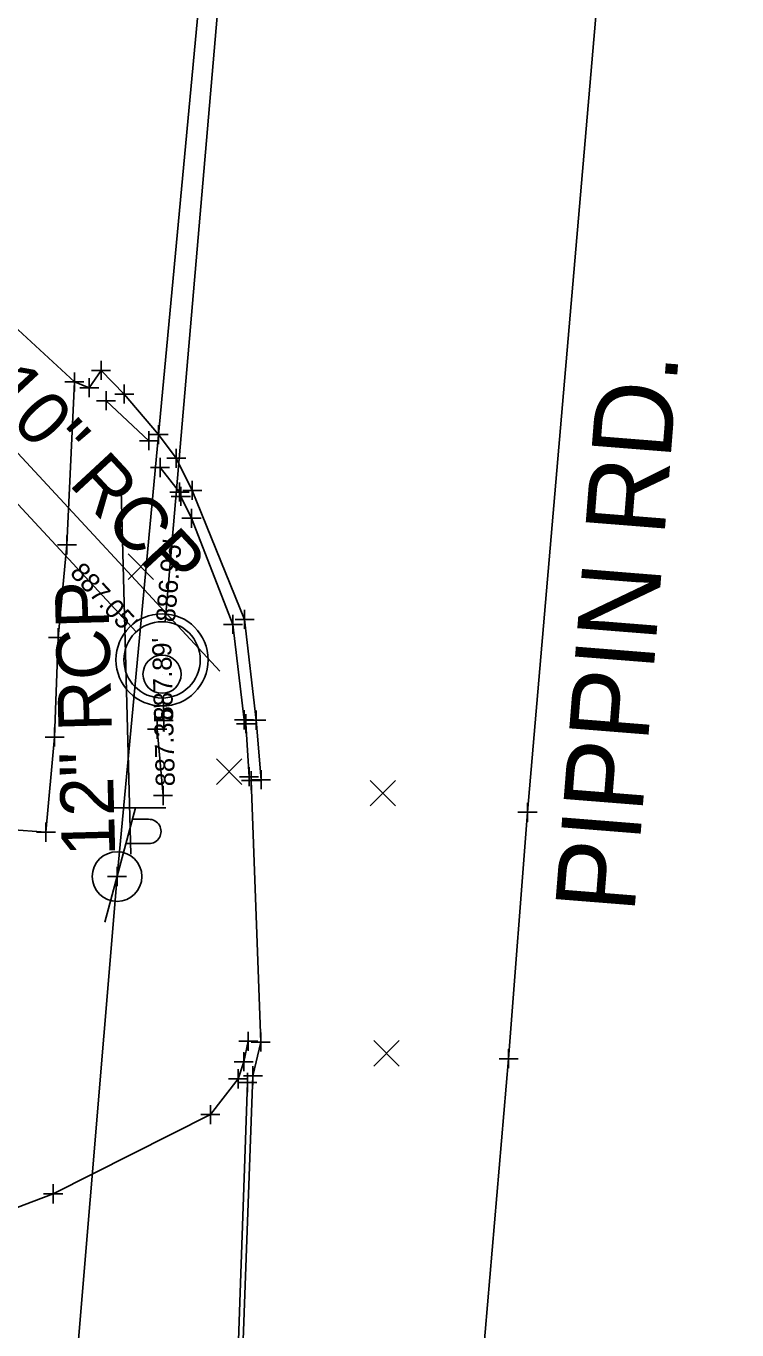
# Model space of a CAD drawing. Extents: x 1380550 to 1381945, y 468927 to 470496.
# Drawn here: x 1381555 to 1381592.3, y 469733.6 to 469802 of the extents above; entities that cross this region are included whole.
import ezdxf

# ---------------------------------------------------------------- set-up
doc = ezdxf.new("R2010")
doc.units = 0
for name, color, linetype in [('DR_X_Cells', 7, 'Continuous'), ('DR_X_Ditch', 7, 'Continuous'), ('DR_X_Elev_Flow', 7, 'Continuous'), ('DR_X_Storm_Sewer', 7, 'Continuous'), ('DR_X_Text', 7, 'Continuous'), ('GK_Drainage_Nodes', 7, 'Continuous'), ('PV_X_COP', 7, 'Continuous'), ('PV_X_Curb', 7, 'Continuous'), ('PV_X_Driveway', 7, 'Continuous'), ('PV_X_EOP', 7, 'Continuous'), ('PV_X_Walk', 7, 'Continuous'), ('RD_X_Text', 7, 'Continuous'), ('SC_Scratch1', 7, 'Continuous'), ('SV_X_Random_Point', 7, 'Continuous'), ('SV_X_Shot_Marker', 7, 'Continuous'), ('UT_X_Electric', 7, 'Continuous'), ('UT_X_Misc_Cells', 7, 'Continuous'), ('UT_X_Telecom', 7, 'Continuous')]:
    doc.layers.add(name, color=color, linetype=linetype)

msp = doc.modelspace()

# ---------------------------------------------------------------- linework, layer by layer
at = {"layer": 'DR_X_Cells'}
for centre, radius in [((1381562.133, 469768.763), 2.417), ((1381562.133, 469768.763), 2), ((1381562.133, 469768.013), 1)]:
    msp.add_circle(centre, radius, dxfattribs=at)
at = {"layer": 'DR_X_Ditch'}
msp.add_lwpolyline([(1381561.875, 469765.127), (1381562.186, 469761.653)], dxfattribs=at)
at = {"layer": 'DR_X_Elev_Flow'}
for p, q in [((1381562.218, 469766.087), (1381562.218, 469765.087)), ((1381561.718, 469765.587), (1381562.718, 469765.587)), ((1381562.218, 469765.587), (1381562.218, 469765.587))]:
    msp.add_line(p, q, dxfattribs=at)
at = {"layer": 'DR_X_Storm_Sewer'}
for p, q in [((1381562.304, 469770.756), (1381570.468, 469866.053)), ((1381551.192, 469780.565), (1381560.773, 469770.23)), ((1381562.218, 469765.587), (1381562.187, 469766.764))]:
    msp.add_line(p, q, dxfattribs=at)
at = {"layer": 'DR_X_Text'}
for p, q in [((1381565.163, 469768.167), (1381552.187, 469782.164)), ((1381559.994, 469777.663), (1381560.505, 469758.584))]:
    msp.add_line(p, q, dxfattribs=at)
at = {"layer": 'GK_Drainage_Nodes'}
for p, q in [((1381562.133, 469770.763), (1381562.133, 469770.763)), ((1381562.133, 469768.763), (1381562.133, 469768.763)), ((1381562.133, 469768.763), (1381562.133, 469768.763)), ((1381562.133, 469768.013), (1381562.133, 469768.013)), ((1381562.133, 469766.763), (1381562.133, 469766.763))]:
    msp.add_line(p, q, dxfattribs=at)
msp.add_circle((1381562.133, 469768.763), 2, dxfattribs=at)
at = {"layer": 'PV_X_COP'}
msp.add_lwpolyline([(1381585.986, 469815.579), (1381581.288, 469760.779), (1381580.3, 469747.86), (1381578.724, 469729.445), (1381576.782, 469708.953), (1381575.288, 469689.792), (1381572.756, 469657.561), (1381569.364, 469615.703), (1381565.36, 469567.235), (1381561.161, 469537.516), (1381558.939, 469486.814), (1381555.385, 469442.034), (1381550.974, 469391.016), (1381547.282, 469345.901), (1381541.953, 469289.547), (1381537.187, 469231.269), (1381533.052, 469168.087), (1381530.317, 469133.741), (1381523.968, 469065.081), (1381520.119, 469021.37), (1381518.183, 469001.306)], dxfattribs=at)
at = {"layer": 'PV_X_Curb'}
for points in [[(1381559.2, 469782.348), (1381561.446, 469780.248)], [(1381562.028, 469778.847), (1381563.047, 469777.556)], [(1381563.117, 469777.334), (1381563.677, 469776.185), (1381565.845, 469770.624), (1381566.43, 469765.622)], [(1381566.528, 469765.416), (1381566.694, 469762.642)], [(1381566.655, 469748.774), (1381566.415, 469747.703), (1381566.122, 469746.805)]]:
    msp.add_lwpolyline(points, dxfattribs=at)
at = {"layer": 'PV_X_Driveway'}
for points in [[(1381566.122, 469746.805), (1381564.669, 469744.932), (1381556.427, 469740.777), (1381548.721, 469737.856), (1381530.445, 469739.354), (1381510.464, 469741.163), (1381499.816, 469742.492)], [(1381566.606, 469746.613), (1381566.048, 469730.586), (1381565.129, 469713.089)]]:
    msp.add_lwpolyline(points, dxfattribs=at)
at = {"layer": 'PV_X_EOP'}
msp.add_lwpolyline([(1381504.028, 469796.448), (1381535.807, 469794.23), (1381542.352, 469793.559), (1381553.913, 469786.695), (1381557.537, 469783.333), (1381558.315, 469783.028), (1381558.933, 469783.936), (1381560.152, 469782.697), (1381561.946, 469780.572), (1381562.877, 469779.327), (1381563.718, 469777.647), (1381566.457, 469770.887), (1381567.072, 469765.604), (1381567.323, 469762.484), (1381566.8, 469762.436), (1381567.306, 469748.735), (1381566.899, 469746.966), (1381566.292, 469730.736), (1381565.481, 469712.75), (1381565.267, 469710.062), (1381564.074, 469691.212), (1381563.724, 469691.131), (1381563.046, 469684.218)], dxfattribs=at)
at = {"layer": 'PV_X_Walk'}
msp.add_lwpolyline([(1381557.537, 469783.333), (1381557.146, 469774.789), (1381556.682, 469769.93), (1381556.498, 469764.719), (1381556.044, 469759.732), (1381552.219, 469760.017)], dxfattribs=at)
at = {"layer": 'SV_X_Random_Point'}
for p, q in [((1381560.354, 469772.978), (1381561.688, 469774.313)), ((1381560.354, 469774.313), (1381561.688, 469772.978)), ((1381564.979, 469762.233), (1381566.313, 469763.568)), ((1381564.979, 469763.568), (1381566.313, 469762.233)), ((1381573.034, 469761.107), (1381574.368, 469762.442)), ((1381573.034, 469762.442), (1381574.368, 469761.107)), ((1381573.233, 469747.473), (1381574.567, 469748.808)), ((1381573.233, 469748.808), (1381574.567, 469747.473))]:
    msp.add_line(p, q, dxfattribs=at)
at = {"layer": 'SV_X_Shot_Marker'}
for p, q in [((1381557.537, 469783.833), (1381557.537, 469782.833)), ((1381557.537, 469783.833), (1381557.537, 469782.833)), ((1381558.433, 469783.936), (1381559.433, 469783.936)), ((1381558.933, 469784.436), (1381558.933, 469783.436)), ((1381558.933, 469783.936), (1381558.933, 469783.936)), ((1381557.037, 469783.333), (1381558.037, 469783.333)), ((1381557.037, 469783.333), (1381558.037, 469783.333)), ((1381557.537, 469783.333), (1381557.537, 469783.333)), ((1381557.537, 469783.333), (1381557.537, 469783.333)), ((1381558.315, 469783.528), (1381558.315, 469782.528)), ((1381560.152, 469783.197), (1381560.152, 469782.197)), ((1381557.815, 469783.028), (1381558.815, 469783.028)), ((1381558.315, 469783.028), (1381558.315, 469783.028)), ((1381559.2, 469782.848), (1381559.2, 469781.848)), ((1381559.652, 469782.697), (1381560.652, 469782.697)), ((1381560.152, 469782.697), (1381560.152, 469782.697)), ((1381558.7, 469782.348), (1381559.7, 469782.348)), ((1381559.2, 469782.348), (1381559.2, 469782.348)), ((1381561.946, 469781.072), (1381561.946, 469780.072)), ((1381561.446, 469780.748), (1381561.446, 469779.748)), ((1381561.446, 469780.572), (1381562.446, 469780.572)), ((1381561.946, 469780.572), (1381561.946, 469780.572)), ((1381560.946, 469780.248), (1381561.946, 469780.248)), ((1381561.446, 469780.248), (1381561.446, 469780.248)), ((1381562.877, 469779.827), (1381562.877, 469778.827)), ((1381562.028, 469779.347), (1381562.028, 469778.347)), ((1381562.377, 469779.327), (1381563.377, 469779.327)), ((1381562.877, 469779.327), (1381562.877, 469779.327)), ((1381561.528, 469778.847), (1381562.528, 469778.847)), ((1381562.028, 469778.847), (1381562.028, 469778.847)), ((1381563.047, 469778.056), (1381563.047, 469777.056)), ((1381563.117, 469777.834), (1381563.117, 469776.834)), ((1381563.218, 469777.647), (1381564.218, 469777.647)), ((1381563.218, 469777.647), (1381564.218, 469777.647)), ((1381563.718, 469778.147), (1381563.718, 469777.147)), ((1381563.718, 469778.147), (1381563.718, 469777.147)), ((1381563.718, 469777.647), (1381563.718, 469777.647)), ((1381563.718, 469777.647), (1381563.718, 469777.647)), ((1381562.547, 469777.556), (1381563.547, 469777.556)), ((1381562.617, 469777.334), (1381563.617, 469777.334)), ((1381563.047, 469777.556), (1381563.047, 469777.556)), ((1381563.117, 469777.334), (1381563.117, 469777.334)), ((1381563.677, 469776.685), (1381563.677, 469775.685)), ((1381563.677, 469776.685), (1381563.677, 469775.685)), ((1381563.177, 469776.185), (1381564.177, 469776.185)), ((1381563.177, 469776.185), (1381564.177, 469776.185)), ((1381563.677, 469776.185), (1381563.677, 469776.185)), ((1381563.677, 469776.185), (1381563.677, 469776.185)), ((1381557.146, 469775.289), (1381557.146, 469774.289)), ((1381556.646, 469774.789), (1381557.646, 469774.789)), ((1381557.146, 469774.789), (1381557.146, 469774.789)), ((1381565.845, 469771.124), (1381565.845, 469770.124)), ((1381565.957, 469770.887), (1381566.957, 469770.887)), ((1381566.457, 469771.387), (1381566.457, 469770.387)), ((1381566.457, 469770.887), (1381566.457, 469770.887)), ((1381556.682, 469770.43), (1381556.682, 469769.43)), ((1381565.345, 469770.624), (1381566.345, 469770.624)), ((1381565.845, 469770.624), (1381565.845, 469770.624)), ((1381556.182, 469769.93), (1381557.182, 469769.93)), ((1381556.682, 469769.93), (1381556.682, 469769.93)), ((1381566.43, 469766.122), (1381566.43, 469765.122)), ((1381566.43, 469766.122), (1381566.43, 469765.122)), ((1381567.072, 469766.104), (1381567.072, 469765.104)), ((1381567.072, 469766.104), (1381567.072, 469765.104)), ((1381561.875, 469765.627), (1381561.875, 469764.627)), ((1381565.93, 469765.622), (1381566.93, 469765.622)), ((1381565.93, 469765.622), (1381566.93, 469765.622)), ((1381566.028, 469765.416), (1381567.028, 469765.416)), ((1381566.43, 469765.622), (1381566.43, 469765.622)), ((1381566.43, 469765.622), (1381566.43, 469765.622)), ((1381566.528, 469765.916), (1381566.528, 469764.916)), ((1381566.528, 469765.416), (1381566.528, 469765.416)), ((1381566.572, 469765.604), (1381567.572, 469765.604)), ((1381566.572, 469765.604), (1381567.572, 469765.604)), ((1381567.072, 469765.604), (1381567.072, 469765.604)), ((1381567.072, 469765.604), (1381567.072, 469765.604)), ((1381555.998, 469764.719), (1381556.998, 469764.719)), ((1381556.498, 469765.219), (1381556.498, 469764.219)), ((1381556.498, 469764.719), (1381556.498, 469764.719)), ((1381561.375, 469765.127), (1381562.375, 469765.127)), ((1381561.875, 469765.127), (1381561.875, 469765.127)), ((1381566.194, 469762.642), (1381567.194, 469762.642)), ((1381566.694, 469763.142), (1381566.694, 469762.142)), ((1381566.694, 469762.642), (1381566.694, 469762.642)), ((1381566.8, 469762.936), (1381566.8, 469761.936)), ((1381567.323, 469762.984), (1381567.323, 469761.984)), ((1381562.186, 469762.153), (1381562.186, 469761.153)), ((1381566.3, 469762.436), (1381567.3, 469762.436)), ((1381566.8, 469762.436), (1381566.8, 469762.436)), ((1381566.823, 469762.484), (1381567.823, 469762.484)), ((1381567.323, 469762.484), (1381567.323, 469762.484)), ((1381561.686, 469761.653), (1381562.686, 469761.653)), ((1381562.186, 469761.653), (1381562.186, 469761.653)), ((1381581.288, 469761.279), (1381581.288, 469760.279)), ((1381580.788, 469760.779), (1381581.788, 469760.779)), ((1381581.288, 469760.779), (1381581.288, 469760.779)), ((1381556.044, 469760.232), (1381556.044, 469759.232)), ((1381555.544, 469759.732), (1381556.544, 469759.732)), ((1381556.044, 469759.732), (1381556.044, 469759.732)), ((1381559.775, 469757.908), (1381559.775, 469756.908)), ((1381559.775, 469757.908), (1381559.775, 469756.908)), ((1381559.275, 469757.408), (1381560.275, 469757.408)), ((1381559.275, 469757.408), (1381560.275, 469757.408)), ((1381559.775, 469757.408), (1381559.775, 469757.408)), ((1381559.775, 469757.408), (1381559.775, 469757.408)), ((1381566.655, 469749.274), (1381566.655, 469748.274)), ((1381567.306, 469749.235), (1381567.306, 469748.235)), ((1381566.155, 469748.774), (1381567.155, 469748.774)), ((1381566.655, 469748.774), (1381566.655, 469748.774)), ((1381566.806, 469748.735), (1381567.806, 469748.735)), ((1381567.306, 469748.735), (1381567.306, 469748.735)), ((1381580.3, 469748.36), (1381580.3, 469747.36)), ((1381565.915, 469747.703), (1381566.915, 469747.703)), ((1381566.415, 469748.203), (1381566.415, 469747.203)), ((1381566.415, 469747.703), (1381566.415, 469747.703)), ((1381579.8, 469747.86), (1381580.8, 469747.86)), ((1381580.3, 469747.86), (1381580.3, 469747.86)), ((1381566.122, 469747.305), (1381566.122, 469746.305)), ((1381566.122, 469747.305), (1381566.122, 469746.305)), ((1381566.399, 469746.966), (1381567.399, 469746.966)), ((1381566.606, 469747.113), (1381566.606, 469746.113)), ((1381566.899, 469747.466), (1381566.899, 469746.466)), ((1381566.899, 469746.966), (1381566.899, 469746.966)), ((1381565.622, 469746.805), (1381566.622, 469746.805)), ((1381565.622, 469746.805), (1381566.622, 469746.805)), ((1381566.106, 469746.613), (1381567.106, 469746.613)), ((1381566.122, 469746.805), (1381566.122, 469746.805)), ((1381566.122, 469746.805), (1381566.122, 469746.805)), ((1381566.606, 469746.613), (1381566.606, 469746.613)), ((1381564.169, 469744.932), (1381565.169, 469744.932)), ((1381564.169, 469744.932), (1381565.169, 469744.932)), ((1381564.669, 469745.432), (1381564.669, 469744.432)), ((1381564.669, 469745.432), (1381564.669, 469744.432)), ((1381564.669, 469744.932), (1381564.669, 469744.932)), ((1381564.669, 469744.932), (1381564.669, 469744.932)), ((1381555.927, 469740.777), (1381556.927, 469740.777)), ((1381556.427, 469741.277), (1381556.427, 469740.277)), ((1381556.427, 469740.777), (1381556.427, 469740.777))]:
    msp.add_line(p, q, dxfattribs=at)
at = {"layer": 'UT_X_Electric'}
msp.add_lwpolyline([(1381665.562, 470247.404), (1381595.795, 470220.833), (1381581.264, 470018.199), (1381571.968, 469887.64), (1381559.775, 469757.408), (1381543.86, 469565.781), (1381529.165, 469390.12), (1381515.279, 469203.101), (1381540.8, 469054.263)], dxfattribs=at)
at = {"layer": 'UT_X_Misc_Cells'}
for p, q in [((1381560.738, 469761.008), (1381559.132, 469755.008)), ((1381562.338, 469761.008), (1381559.138, 469761.008)), ((1381560.578, 469760.408), (1381561.428, 469760.408)), ((1381560.237, 469759.133), (1381561.428, 469759.133))]:
    msp.add_line(p, q, dxfattribs=at)
msp.add_circle((1381559.775, 469757.408), 1.3, dxfattribs=at)
msp.add_arc((1381561.441, 469759.771), 0.638, 268.8767, 91.1233, dxfattribs=at)
at = {"layer": 'UT_X_Telecom'}
msp.add_lwpolyline([(1381665.562, 470247.404), (1381595.346, 470217.51), (1381581.264, 470018.199), (1381571.968, 469887.64), (1381559.775, 469757.408), (1381543.86, 469565.781), (1381529.165, 469390.12), (1381515.279, 469203.101), (1381540.8, 469054.263)], dxfattribs=at)

# ---------------------------------------------------------------- texts
at = {"layer": 'DR_X_Text'}
for s, rotation, p in [('10" RCP', 312.83291, (1381552.75, 469782.768)), ('12" RCP', 91.53301, (1381559.683, 469758.502))]:
    msp.add_text(s, height=2.8, rotation=rotation, dxfattribs=at).set_placement(p)
at = {"layer": 'RD_X_Text'}
msp.add_text('PIPPIN RD.', height=4.1667, rotation=85.44278, dxfattribs=at).set_placement((1381586.884, 469755.439))
at = {"layer": 'SC_Scratch1'}
for s, rotation, p in [("886.95'", 85.10335, (1381562.802, 469770.713)), ("887.05'", 312.83291, (1381557.257, 469773.287)), ("887.89'", 91.53301, (1381562.718, 469765.6)), ("887.35'", 91.53301, (1381562.81, 469762.146))]:
    msp.add_text(s, height=1, rotation=rotation, dxfattribs=at).set_placement(p)

doc.saveas('drawing.dxf')
